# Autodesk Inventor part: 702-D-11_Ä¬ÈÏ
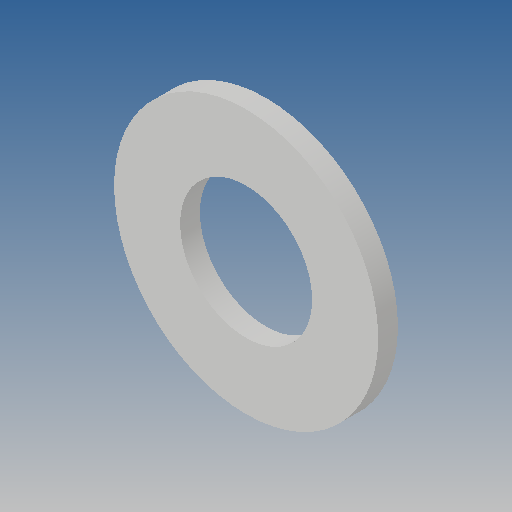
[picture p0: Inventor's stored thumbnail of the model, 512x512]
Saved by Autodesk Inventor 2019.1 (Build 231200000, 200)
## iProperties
Created: 2010-06
Part Number: 702-D-11_Ä¬ÈÏ
Material: Ogólny
Document SubType Name: Modeling
Designer: CADENGINEERING4
Density: 1 g/cm^3
Appearance: Domyślna
Author: CADENGINEERING4
Revision Number: ÈÎºÎ
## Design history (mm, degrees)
feature "NONE"
node "Bryła1"
